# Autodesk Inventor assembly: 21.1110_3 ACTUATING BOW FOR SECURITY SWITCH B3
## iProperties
Created: 2007-05
Part Number: 21.1110_3 ACTUATING BOW FOR SECURITY SWITCH B3
Document SubType Name: Assembly
Designer: Andy Moles
Author: Andy Moles
